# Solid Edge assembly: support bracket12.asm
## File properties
Author: Deepak Maini
Template: normal.asm
Last saved by: Robert a Rhodes jr
Revision: 3
Application: Solid Edge
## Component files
adjusting_nut_handle.par
adjusting_screw_guide.par
Stock_support_base.par
thrust_bearing.par
adjusting_screw_nut.par
support_adjusting_screw.par
support_roller_bracket.par
stock_support_roller.par
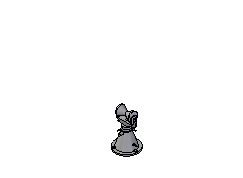
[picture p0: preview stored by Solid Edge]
